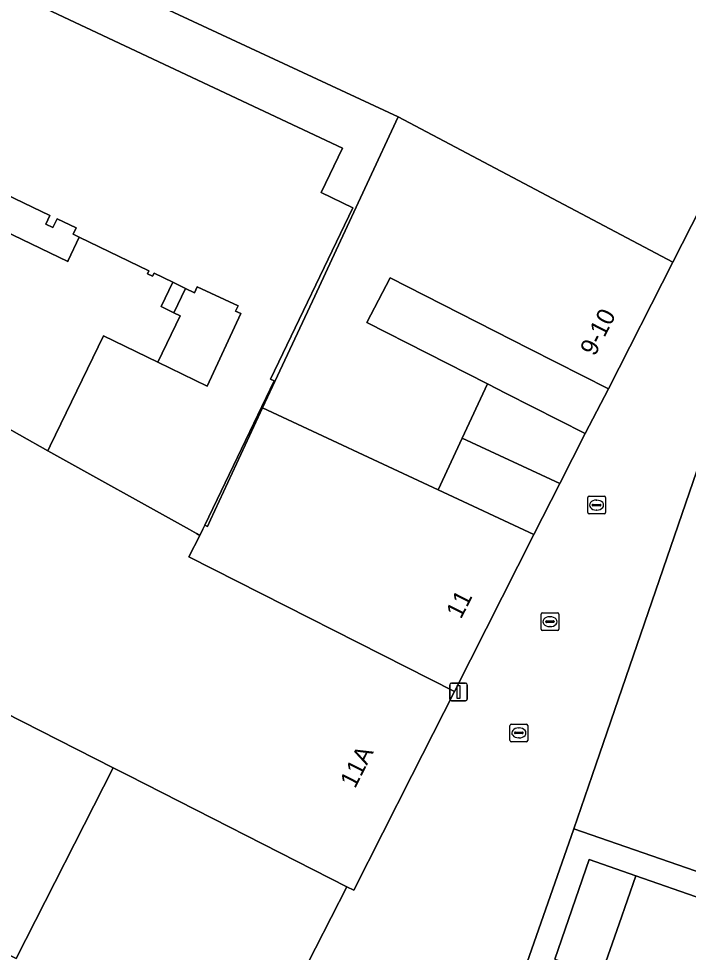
# Model space of a CAD drawing. Extents: x 160349 to 161355, y 381727 to 382854.
# Drawn here: x 160618.4 to 160656.3, y 382240 to 382292.8 of the extents above; entities that cross this region are included whole.
import ezdxf

# ---------------------------------------------------------------- set-up
doc = ezdxf.new("R2010")
doc.units = 0
for name, color, linetype in [('IMGEO_Erf', 7, 'Continuous'), ('IMGEO_Kolk', 7, 'Continuous'), ('IMGEO_Lichtmast', 7, 'Continuous'), ('IMGEO_Pand', 7, 'Continuous'), ('IMGEO_Pand_nummerreeks', 7, 'Continuous'), ('IMGEO_Rijbaan_lokaal_open', 7, 'Continuous'), ('IMGEO_Rioolput', 7, 'Continuous'), ('IMGEO_Voetpad_op_trap', 7, 'Continuous'), ('IMGEO_Voetpad_open', 7, 'Continuous')]:
    doc.layers.add(name, color=color, linetype=linetype)

msp = doc.modelspace()

# ---------------------------------------------------------------- linework, layer by layer
at = {"layer": 'IMGEO_Erf'}
for points in [[(160602.684, 382304.568), (160601.691, 382305.031), (160601.354, 382305.194), (160600.114, 382302.653), (160636.742, 382285.453), (160635.529, 382282.942), (160637.325, 382282.078), (160632.67, 382272.4), (160632.865, 382272.306), (160628.955, 382264.141), (160629.092, 382264.073), (160629.265, 382264.444), (160632.219, 382270.779), (160635.163, 382277.094), (160636.369, 382279.681), (160639.886, 382287.223), (160625.056, 382294.138)], [(160639.431, 382278.124), (160638.106, 382275.598), (160644.93, 382272.13), (160645.988, 382271.592), (160650.445, 382269.326), (160651.77, 382271.852), (160647.313, 382274.118)], [(160630.985, 382276.098), (160630.685, 382276.237), (160630.825, 382276.536), (160628.525, 382277.605), (160628.368, 382277.278), (160627.864, 382277.521), (160627.203, 382276.15), (160627.563, 382275.976), (160626.298, 382273.351), (160629.083, 382272.008)], [(160636.978, 382243.724), (160624.635, 382250), (160623.772, 382250.439), (160618.279, 382239.673), (160604.886, 382246.452), (160610.389, 382257.243), (160610.3, 382257.288), (160606.582, 382250), (160600.025, 382237.133), (160619.255, 382235.929), (160618.701, 382227.096), (160628.15, 382226.469), (160628.19, 382226.548), (160620.242, 382227.418), (160620.574, 382232.705), (160630.77, 382231.589)]]:
    msp.add_lwpolyline(points, close=True, dxfattribs=at)
for points in [[(160594.887, 382291.692), (160621.195, 382279.049), (160621.221, 382279.105), (160621.852, 382280.417), (160621.509, 382280.583), (160621.68, 382280.944), (160620.592, 382281.465), (160620.354, 382280.969), (160619.962, 382281.157), (160620.195, 382281.644), (160616.209, 382283.552)], [(160670.547, 382238.283), (160657.113, 382243.023), (160653.317, 382244.343), (160652.373, 382241.628), (160651.361, 382238.718)]]:
    msp.add_lwpolyline(points, dxfattribs=at)
at = {"layer": 'IMGEO_Kolk'}
for p, q in [((160650.671, 382265.782), (160651.523, 382265.782)), ((160650.596, 382264.856), (160650.596, 382265.708)), ((160650.855, 382265.276), (160650.855, 382265.288)), ((160651.293, 382265.239), (160650.895, 382265.239)), ((160650.898, 382265.325), (160651.296, 382265.325)), ((160651.084, 382265.562), (160651.109, 382265.562)), ((160651.339, 382265.288), (160651.339, 382265.276)), ((160651.597, 382265.708), (160651.597, 382264.856)), ((160651.523, 382264.782), (160650.671, 382264.782)), ((160651.107, 382265.002), (160651.082, 382265.002)), ((160646.203, 382251.987), (160646.203, 382252.839)), ((160646.278, 382252.913), (160647.13, 382252.913)), ((160646.691, 382252.693), (160646.716, 382252.693)), ((160647.204, 382252.839), (160647.204, 382251.987)), ((160646.462, 382252.407), (160646.462, 382252.419)), ((160646.9, 382252.37), (160646.502, 382252.37)), ((160646.505, 382252.456), (160646.903, 382252.456)), ((160646.714, 382252.133), (160646.689, 382252.133)), ((160646.946, 382252.419), (160646.946, 382252.407)), ((160647.13, 382251.913), (160646.278, 382251.913))]:
    msp.add_line(p, q, dxfattribs=at)
for points in [[(160650.671, 382265.782), (160651.523, 382265.782)], [(160650.596, 382264.856), (160650.596, 382265.708)], [(160651.597, 382265.708), (160651.597, 382264.856)], [(160651.523, 382264.782), (160650.671, 382264.782)], [(160646.203, 382251.987), (160646.203, 382252.839)], [(160646.278, 382252.913), (160647.13, 382252.913)], [(160647.204, 382252.839), (160647.204, 382251.987)], [(160647.13, 382251.913), (160646.278, 382251.913)]]:
    msp.add_lwpolyline(points, dxfattribs=at)
for centre, radius, start, end in [((160650.673, 382265.706), 0.0765, 91.552, 178.448), ((160650.673, 382265.706), 0.0765, 91.552, 178.448), ((160651.521, 382265.706), 0.0765, 1.552, 88.448), ((160651.521, 382265.706), 0.0765, 1.552, 88.448), ((160650.895, 382265.285), 0.0403, 85.8775, 175.7526), ((160650.892, 382265.275), 0.0366, 178.938, 274.7102), ((160651.296, 382265.282), 0.043, 264.8664, 352.4533), ((160651.3, 382265.287), 0.0386, 1.7309, 96.639), ((160650.673, 382264.858), 0.0765, 181.552, 268.448), ((160650.673, 382264.858), 0.0765, 181.552, 268.448), ((160651.521, 382264.858), 0.0765, 271.552, 358.448), ((160651.521, 382264.858), 0.0765, 271.552, 358.448), ((160646.28, 382252.837), 0.0765, 91.552, 178.448), ((160646.28, 382252.837), 0.0765, 91.552, 178.448), ((160647.128, 382252.837), 0.0765, 1.552, 88.448), ((160647.128, 382252.837), 0.0765, 1.552, 88.448), ((160646.502, 382252.416), 0.0403, 85.8775, 175.7526), ((160646.499, 382252.406), 0.0366, 178.938, 274.7102), ((160646.903, 382252.413), 0.043, 264.8664, 352.4533), ((160646.907, 382252.418), 0.0386, 1.7309, 96.639), ((160646.28, 382251.989), 0.0765, 181.552, 268.448), ((160646.28, 382251.989), 0.0765, 181.552, 268.448), ((160647.128, 382251.989), 0.0765, 271.552, 358.448), ((160647.128, 382251.989), 0.0765, 271.552, 358.448)]:
    msp.add_arc(centre, radius, start, end, dxfattribs=at)
for centre, major_axis, ratio, start_param, end_param in [((160651.083, 382265.282), (-0.387, 0.002), 0.722429, 4.712389, 7.853982), ((160651.108, 382265.282), (-0.39, 0.002), 0.717154, 1.570796, 4.712389), ((160646.69, 382252.413), (-0.387, 0.002), 0.722429, 4.712389, 7.853982), ((160646.715, 382252.413), (-0.39, 0.002), 0.717154, 1.570796, 4.712389)]:
    msp.add_ellipse(centre, major_axis=major_axis, ratio=ratio, start_param=start_param, end_param=end_param, dxfattribs=at)
at = {"layer": 'IMGEO_Lichtmast'}
for p, q in [((160642.899, 382255.224), (160643.689, 382255.224)), ((160643.689, 382255.224), (160642.899, 382255.224)), ((160642.799, 382254.324), (160642.799, 382255.124)), ((160642.799, 382255.124), (160642.799, 382254.324)), ((160643.789, 382255.124), (160643.789, 382254.324)), ((160643.789, 382254.324), (160643.789, 382255.124)), ((160643.689, 382254.224), (160642.899, 382254.224)), ((160642.899, 382254.224), (160643.689, 382254.224))]:
    msp.add_line(p, q, dxfattribs=at)
msp.add_lwpolyline([(160643.219, 382255.099), (160643.369, 382255.099), (160643.369, 382254.349), (160643.219, 382254.349), (160643.219, 382255.099)], dxfattribs=at)
for centre, start, end in [((160642.899, 382255.124), 90, 180), ((160642.899, 382255.124), 90, 180), ((160643.689, 382255.124), 0, 90), ((160643.689, 382255.124), 360, 90), ((160642.899, 382254.324), 180, 270), ((160642.899, 382254.324), 180, 270), ((160643.689, 382254.324), 270, 0), ((160643.689, 382254.324), 270, 0)]:
    msp.add_arc(centre, 0.1, start, end, dxfattribs=at)
at = {"layer": 'IMGEO_Pand'}
for points in [[(160648.237, 382305.19), (160647.931, 382305.351), (160640.311, 382309.261), (160635.029, 382311.972), (160634.167, 382312.414), (160625.056, 382294.138), (160639.886, 382287.223), (160655.407, 382279.006), (160660.19, 382288.413), (160664.391, 382296.677)], [(160655.407, 382279.006), (160639.886, 382287.223), (160636.369, 382279.681), (160635.163, 382277.094), (160632.219, 382270.779), (160642.143, 382266.152), (160643.497, 382269.058), (160644.93, 382272.13), (160638.106, 382275.598), (160639.431, 382278.124), (160647.313, 382274.118), (160651.77, 382271.852)], [(160650.445, 382269.326), (160645.988, 382271.592), (160644.93, 382272.13), (160643.497, 382269.058), (160649.013, 382266.499)], [(160647.558, 382263.627), (160642.143, 382266.152), (160632.219, 382270.779), (160629.265, 382264.444), (160629.092, 382264.073), (160628.955, 382264.141), (160628.845, 382263.924), (160628.666, 382263.571), (160628.047, 382262.35), (160643.057, 382254.744)], [(160628.047, 382262.35), (160628.666, 382263.571), (160628.475, 382263.678), (160628.076, 382263.899), (160620.078, 382268.352), (160616.85, 382270.149), (160616.565, 382269.591), (160614.123, 382264.804), (160610.3, 382257.288), (160610.389, 382257.243), (160623.772, 382250.439), (160624.635, 382250), (160636.978, 382243.724), (160637.372, 382243.524), (160640.653, 382250), (160643.057, 382254.744)], [(160649.013, 382266.499), (160643.497, 382269.058), (160642.143, 382266.152), (160647.558, 382263.627)], [(160678.823, 382244.8), (160681.335, 382250), (160683.018, 382253.486), (160676.269, 382256.914), (160676.429, 382257.23), (160658.261, 382266.458), (160656.765, 382267.218), (160650.851, 382250), (160649.821, 382247), (160667.947, 382240.726), (160668.067, 382240.875), (160670.969, 382240.037), (160674.502, 382246.994)], [(160623.772, 382250.439), (160610.389, 382257.243), (160604.886, 382246.452), (160618.279, 382239.673)], [(160653.317, 382244.343), (160650.687, 382245.257), (160648.731, 382239.631), (160651.361, 382238.718), (160652.373, 382241.628)]]:
    msp.add_lwpolyline(points, close=True, dxfattribs=at)
msp.add_lwpolyline([(160616.209, 382283.552), (160620.195, 382281.644), (160619.962, 382281.157), (160620.354, 382280.969), (160620.592, 382281.465), (160621.68, 382280.944), (160621.509, 382280.583), (160621.852, 382280.417), (160625.79, 382278.518), (160625.708, 382278.346), (160625.996, 382278.208), (160626.078, 382278.379), (160627.14, 382277.869), (160627.864, 382277.521), (160628.368, 382277.278), (160628.525, 382277.605), (160630.825, 382276.536), (160630.685, 382276.237), (160630.985, 382276.098), (160629.083, 382272.008), (160626.298, 382273.351), (160623.212, 382274.839), (160620.207, 382268.622), (160620.078, 382268.352), (160628.076, 382263.899), (160628.475, 382263.678), (160628.666, 382263.571), (160628.845, 382263.924), (160628.955, 382264.141), (160632.865, 382272.306), (160632.67, 382272.4), (160637.325, 382282.078), (160635.529, 382282.942), (160636.742, 382285.453), (160600.114, 382302.653)], dxfattribs=at)
at = {"layer": 'IMGEO_Rijbaan_lokaal_open'}
for points in [[(160706.936, 382366.68), (160701.539, 382369.381), (160692.321, 382351.324), (160688.36, 382343.941), (160684.72, 382336.736), (160680.548, 382328.477), (160673.518, 382314.63), (160668.997, 382305.738), (160664.391, 382296.677), (160660.19, 382288.413), (160655.407, 382279.006), (160651.77, 382271.852), (160650.445, 382269.326), (160649.013, 382266.499), (160647.558, 382263.627), (160643.057, 382254.744), (160640.653, 382250), (160637.372, 382243.524), (160636.978, 382243.724), (160630.77, 382231.589)], [(160624.54, 382174.828), (160649.821, 382247), (160650.851, 382250), (160656.765, 382267.218), (160658.261, 382266.458), (160660.439, 382271.044), (160660.552, 382271.281), (160658.906, 382272.136), (160658.687, 382272.249), (160665.393, 382285.374), (160672.027, 382298.356), (160678.661, 382311.34), (160685.295, 382324.324)], [(160616.85, 382270.149), (160620.078, 382268.352), (160620.207, 382268.622), (160623.212, 382274.839), (160626.298, 382273.351), (160627.563, 382275.976), (160627.203, 382276.15), (160626.479, 382276.499), (160627.14, 382277.869), (160626.078, 382278.379), (160625.996, 382278.208), (160625.708, 382278.346), (160625.79, 382278.518), (160621.852, 382280.417), (160621.221, 382279.105), (160621.195, 382279.049), (160594.887, 382291.692)]]:
    msp.add_lwpolyline(points, dxfattribs=at)
at = {"layer": 'IMGEO_Rioolput'}
for p, q in [((160647.961, 382258.268), (160647.961, 382259.12)), ((160648.036, 382259.194), (160648.888, 382259.194)), ((160648.449, 382258.974), (160648.474, 382258.974)), ((160648.962, 382259.12), (160648.962, 382258.268)), ((160648.22, 382258.688), (160648.22, 382258.7)), ((160648.658, 382258.651), (160648.26, 382258.651)), ((160648.263, 382258.737), (160648.661, 382258.737)), ((160648.472, 382258.414), (160648.447, 382258.414)), ((160648.704, 382258.7), (160648.704, 382258.688)), ((160648.888, 382258.194), (160648.036, 382258.194))]:
    msp.add_line(p, q, dxfattribs=at)
for points in [[(160647.961, 382258.268), (160647.961, 382259.12)], [(160648.036, 382259.194), (160648.888, 382259.194)], [(160648.962, 382259.12), (160648.962, 382258.268)], [(160648.888, 382258.194), (160648.036, 382258.194)]]:
    msp.add_lwpolyline(points, dxfattribs=at)
for centre, radius, start, end in [((160648.038, 382259.118), 0.0765, 91.552, 178.448), ((160648.038, 382259.118), 0.0765, 91.552, 178.448), ((160648.886, 382259.118), 0.0765, 1.552, 88.448), ((160648.886, 382259.118), 0.0765, 1.552, 88.448), ((160648.26, 382258.697), 0.0403, 85.8775, 175.7526), ((160648.257, 382258.687), 0.0366, 178.938, 274.7102), ((160648.661, 382258.694), 0.043, 264.8664, 352.4533), ((160648.665, 382258.699), 0.0386, 1.7309, 96.639), ((160648.038, 382258.27), 0.0765, 181.552, 268.448), ((160648.038, 382258.27), 0.0765, 181.552, 268.448), ((160648.886, 382258.27), 0.0765, 271.552, 358.448), ((160648.886, 382258.27), 0.0765, 271.552, 358.448)]:
    msp.add_arc(centre, radius, start, end, dxfattribs=at)
for centre, major_axis, ratio, start_param, end_param in [((160648.448, 382258.694), (-0.387, 0.002), 0.722429, 4.712389, 7.853982), ((160648.473, 382258.694), (-0.39, 0.002), 0.717154, 1.570796, 4.712389)]:
    msp.add_ellipse(centre, major_axis=major_axis, ratio=ratio, start_param=start_param, end_param=end_param, dxfattribs=at)
at = {"layer": 'IMGEO_Voetpad_op_trap'}
msp.add_lwpolyline([(160627.864, 382277.521), (160627.14, 382277.869), (160626.479, 382276.499), (160627.203, 382276.15)], close=True, dxfattribs=at)
at = {"layer": 'IMGEO_Voetpad_open'}
for points in [[(160675.465, 382238.124), (160667.947, 382240.726), (160649.821, 382247), (160624.54, 382174.828)], [(160648.731, 382239.631), (160650.687, 382245.257), (160653.317, 382244.343), (160657.113, 382243.023), (160670.547, 382238.283)]]:
    msp.add_lwpolyline(points, dxfattribs=at)

# ---------------------------------------------------------------- texts
at = {"layer": 'IMGEO_Pand_nummerreeks'}
for s, rotation, p in [('9-10', 63.054, (160651.002, 382273.651)), ('11', 63.1285, (160643.429, 382258.799)), ('11A', 63.1285, (160637.438, 382249.228))]:
    msp.add_text(s, height=1, rotation=rotation, dxfattribs=at).set_placement(p)

doc.saveas('drawing.dxf')
